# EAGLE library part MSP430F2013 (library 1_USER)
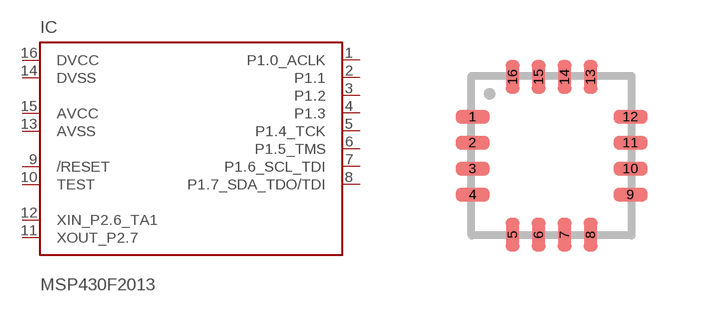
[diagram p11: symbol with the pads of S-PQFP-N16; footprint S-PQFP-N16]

Designator prefix IC

## MSP430F2013  [S-PQFP-N16]
1  P1.0_ACLK
2  P1.1
3  P1.2
4  P1.3
5  P1.4_TCK
6  P1.5_TMS
7  P1.6_SCL_TDI
8  P1.7_SDA_TDO/TDI
9  /RESET  in
10  TEST  in
11  XOUT_P2.7
12  XIN_P2.6_TA1
13  AVSS  pwr
14  DVSS  pwr
15  AVCC  pwr
16  DVCC  pwr

## Footprint S-PQFP-N16 (pad centres in mm)
smd 0.85 x 0.35: 1 -1.975,0.975; 2 -1.975,0.325; 3 -1.975,-0.325; 4 -1.975,-0.975; 9 1.975,-0.975; 10 1.975,-0.325; 11 1.975,0.325; 12 1.975,0.975
smd 0.35 x 0.85: 5 -0.975,-1.975; 6 -0.325,-1.975; 7 0.325,-1.975; 8 0.975,-1.975; 13 0.975,1.975; 14 0.325,1.975; 15 -0.325,1.975; 16 -0.975,1.975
